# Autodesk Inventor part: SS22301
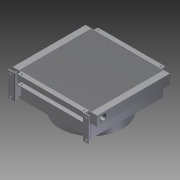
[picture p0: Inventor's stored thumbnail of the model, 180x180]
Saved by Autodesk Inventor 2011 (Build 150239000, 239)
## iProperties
Created: 2011-08
Part Number: SS22301
Document SubType Name: Modeling
Designer: khramov
Density: 1 g/cm^3
Author: khramov
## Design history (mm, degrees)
sketch "Эскиз1"
  geometry: L1 (0, 0)-(54, 0); L2 (538, 0)-(538, -464); L3 (538, -464)-(484, -464); L4 (0, -464)-(0, 0); L5 (0, -232)-(538, -232); L6 (54, 0)-(54, 25); L7 (54, 25)-(484, 25); L8 (484, 25)-(484, 0); L9 (484, 0)-(538, 0); L10 (54, -464)-(54, -489); L11 (54, -489)-(484, -489); L12 (484, -489)-(484, -464); L13 (54, -464)-(0, -464); L14 (70, 12.5)-(468, 12.5); L15 (468, 12.5)-(468, -476.5); L16 (468, -476.5)-(70, -476.5); L17 (70, -476.5)-(70, 12.5); L18 (269, 25)-(269, -489); C1 r 4.5 at (70, 12.5); C2 r 4.5 at (468, 12.5); C3 r 4.5 at (468, -476.5); C4 r 4.5 at (70, -476.5)
  constraints: 36 end point, 7 parallel, 7 perpendicular, 4 centre point, 4 coincident, 4 midpoint, 4 symmetric about line, 3 horizontal, 1 point on line
  dimensions: "d4" = 9 diameter of C4; "d5" = 9 diameter of C3; "d7" = 9 diameter of C1; "d38" = 538 distance between parallel lines of L2 L4; "d39" = 430 distance of L6.end L7.end; "d40" = 54 distance between parallel lines of L6 L4; "d41" = 25 distance of L1.end L6.end; "d42" = 514 distance between parallel lines of L11 L7; "d43" = 489 distance of L16.end L14.start; "d44" = 244.5 distance between parallel lines of L14 L5; "d45" = 398 distance of L14.start L14.end; "d46" = 199 distance between parallel lines of L18 L15; "d47" = 9 diameter of C2
extrude "Выдавливание1" new body sketch "Эскиз1" distance "d13" = 63; taper "d14" = 0 deg
sketch "Эскиз2"
  geometry: L1 (0, 0)-(54, 0) reference; L2 (54, -489)-(54, -464) reference; L3 (484, -464)-(484, -489) reference; L4 (538, -464)-(484, -464) reference; L5 (39, -3)-(499, -3); L6 (499, -3)-(499, -461); L7 (499, -461)-(39, -461); L8 (39, -461)-(39, -3)
  constraints: 8 end point, 2 parallel, 1 horizontal, 1 perpendicular
  dimensions: "d15" = 3 distance between parallel lines of L5 L1; "d16" = 3 distance between parallel lines of L7 L4; "d17" = 15 distance between parallel lines of L6 L3; "d18" = 15 distance between parallel lines of L2 L8
extrude "Выдавливание2" cut sketch "Эскиз2" distance "d19" = 2; taper "d20" = 0 deg
sketch "Эскиз3"
  geometry: L1 (-63, 25)-(-63, 0) reference; L2 (0, 25)-(0, 0) reference; L3 (0, 25)-(-63, 25) reference; L4 (-57, 25)-(-6, 25); L5 (-6, 25)-(-6, 0); L6 (-6, 0)-(-57, 0); L7 (-57, 0)-(-57, 25); L8 (0, -489)-(-63, -489) reference; L9 (-57, -489)-(-6, -489); L10 (-6, -489)-(-6, -464); L11 (-6, -464)-(-57, -464); L12 (-57, -464)-(-57, -489); L13 (0, 0)-(0, -464) reference; L14 (-63, 0)-(-63, -464) reference
  constraints: 16 end point, 4 parallel, 2 horizontal, 2 perpendicular, 2 point on line
  dimensions: "d21" = 6 distance between parallel lines of L7 L1; "d22" = 6 distance between parallel lines of L2 L5; "d23" = 25 distance between parallel lines of L6 L3; "d24" = 25 distance of L9.end L10.end; "d25" = 6 distance between parallel lines of L13 L10; "d26" = 6 distance between parallel lines of L14 L12
extrude "Выдавливание3" cut sketch "Эскиз3" stored distance "d27" = 2; taper "d28" = 0 deg
sketch "Эскиз4"
  geometry: L1 (0, 0)-(-54, 0) reference; L2 (-54, 0)-(-54, 25) reference; L3 (-484, 25)-(-484, 0) reference; L4 (-494, 0)-(-44, 0); L5 (-44, 0)-(-44, -464); L6 (-44, -464)-(-494, -464); L7 (-494, -464)-(-494, 0)
  constraints: 8 end point, 2 parallel, 1 horizontal, 1 perpendicular, 1 point on line
  dimensions: "d48" = 464 distance of L4.end L5.end; "d49" = 10 distance between parallel lines of L3 L7; "d50" = 10 distance between parallel lines of L2 L5
extrude "Выдавливание4" join sketch "Эскиз4" distance "d51" = 90; taper "d52" = 0 deg
sketch "Эскиз5"
  geometry: L1 (-494, 0)-(-44, -464); L2 (-44, 0)-(-494, -464); C1 r 200 at (-269, -232); 1 further point
  constraints: 4 end point, 1 centre point, 1 midpoint
  dimensions: "d53" = 400 diameter of C1
extrude "Выдавливание5" join sketch "Эскиз5" distance "d54" = 70; taper "d55" = 0 deg
sketch "Эскиз6"
  geometry: L1 (-269, -232)-(-269, -734.409); L2 (-484, -489)-(-54, -489) reference; L3 (-538, -464)-(-494, -464) reference; L4 (-491.5, -464)-(-491.5, -494); L5 (-497.5, -500)-(-526.5, -500); L6 (-526.5, -500)-(-526.5, -506); L7 (-526.5, -506)-(-491.5, -506); L8 (-485.5, -500)-(-485.5, -464); L9 (-511.5, -503.753)-(-511.5, -569.856); L10 (-11.5, -500)-(-11.5, -506); L11 (-11.5, -506)-(-46.5, -506); L12 (-40.5, -500)-(-11.5, -500); L13 (-46.5, -464)-(-46.5, -494); L14 (-52.5, -500)-(-52.5, -464); L15 (-26.5, -503.753)-(-26.5, -569.856); L16 (-491.5, -464)-(-485.5, -464); L17 (-538, -464)-(-484, -464) reference; L18 (-52.5, -464)-(-46.5, -464); L19 (-54, -464)-(0, -464) reference; C1 r 200 at (-269, -232) reference; A1 r 6 centre (-497.5, -494) between (-497.5, -500) and (-491.5, -494); A2 r 6 centre (-491.5, -500) between (-491.5, -506) and (-485.5, -500); A3 r 6 centre (-40.5, -494) between (-46.5, -494) and (-40.5, -500); A4 r 6 centre (-46.5, -500) between (-52.5, -500) and (-46.5, -506); 2 further points
  constraints: 31 end point, 13 symmetric about line, 8 point on circle, 4 centre point, 4 tangent, 3 parallel, 2 collinear, 2 perpendicular, 1 equal radius, 1 point on line, 2 other
  dimensions: "d56" = 6 distance of L5.end L6.end; "d57" = 6 distance between parallel lines of L4 L8; "d59" = 15 distance between parallel lines of L9 L6; "d60" = 20 distance between parallel lines of L4 L9; "d62" = 6 radius of A1; "d75" = 485 distance between parallel lines of L9 L15
extrude "Выдавливание6" join sketch "Эскиз6" distance "d63" = 166; taper "d65" = 0 deg; dims "d64" = 1, "d66" = 0
sketch "Эскиз7"
  geometry: L1 (-500, 15)-(-15, 15); L2 (-15, 15)-(-15, 141); L3 (-15, 141)-(-500, 141); L4 (-500, 141)-(-500, 15); L5 (-457.5, 236)-(-57.5, 236) reference; L6 (-257.5, 236)-(-257.5, 402.493); L7 (-472.5, 13)-(-42.5, 13) reference; C1 r 6.5 at (-500, 141); C2 r 6.5 at (-500, 15); C3 r 6.5 at (-15, 141); C4 r 6.5 at (-15, 15); 1 further point
  constraints: 10 end point, 4 centre point, 4 coincident, 2 parallel, 2 perpendicular, 1 horizontal, 1 midpoint
  dimensions: "d67" = 13 diameter of C1; "d68" = 13 diameter of C2; "d69" = 13 diameter of C3; "d70" = 13 diameter of C4; "d71" = 485 distance of L2.end L3.end; "d72" = 126 distance of L3.end L1.start; "d73" = 242.5 distance between parallel lines of L6 L4; "d76" = 2 distance between parallel lines of L1 L7
extrude "Выдавливание7" cut sketch "Эскиз7" distance "d77" = 10; taper "d78" = 0 deg
sketch "Эскиз8"
  geometry: L1 (-166, 15.676)-(-77.058, 26.142); L2 (-77.058, 26.142)-(-77.058, 42); L3 (-166, 42)-(-166, 15.676); L4 (-166, 42)-(-77.058, 42); L5 (-23.748, 26.142)-(-23.748, 42); L6 (-23.748, 42)-(-12.683, 42); L7 (-23.748, 26.142)-(-10, 16.534); L8 (-10, 0)-(0, 0); L9 (0, 0)-(0, 42); L10 (0, 42)-(-23.748, 42); L11 (-10, 16.534)-(-10, 0); 1 further point
  constraints: 22 end point, 3 perpendicular, 1 vertical
  dimensions: "d79" = 10 distance between parallel lines of L9 L11
extrude "Выдавливание8" cut sketch "Эскиз8" stored distance "d80" = 10; taper "d81" = 0 deg
sketch "Эскиз9"
  geometry: L1 (-166, 6)-(-166, 36) reference; L2 (-166, 8.721)-(-166, 36); L3 (-166, 36)-(-77.058, 36); L4 (-77.058, 20.142)-(-77.058, 36) reference; L5 (-77.058, 36)-(-77.058, 20.142); L6 (-77.058, 20.142)-(-166, 9.676); L7 (-77.058, 20.142)-(-166, 9.676) reference; L8 (0, 36)-(0, -6); L9 (0, 36)-(0, 0) reference; L10 (0, -6)-(-10, -6); L11 (-10, -6)-(-10, 0) reference; L12 (-10, -6)-(-10, 10.534); L13 (-10, 10.534)-(-23.748, 20.142); L14 (-10, 10.534)-(-23.748, 20.142) reference; L15 (-23.748, 20.142)-(-23.748, 36); L16 (-153, 36)-(0, 36) reference; L17 (-23.748, 36)-(0, 36); 1 further point
  constraints: 20 end point, 6 collinear, 2 parallel, 2 perpendicular, 2 point on line
extrude "Выдавливание9" cut sketch "Эскиз9" stored distance "d82" = 10; taper "d83" = 0 deg
sketch "Эскиз10"
  geometry: L1 (0, 464)-(63, 464) reference; L2 (0, 0)-(63, 0) reference; L3 (31.5, 464)-(31.5, 0); L4 (-80, -42)-(76, -42) reference; 1 further point
  constraints: 2 end point, 2 midpoint, 1 point on line
  dimensions: "d104" = 468.5 distance from line of L4 point (31.5, 426.5)
hole "Отверстие1" sketch "Эскиз10" at (31.5, 426.5) diameter "d86" = 38.952; stored, may be unused: countersink angle "d90" = 90 deg, drill point angle "d92" = 118 deg; dims "d87" = 45, "d88" = 42, "d89" = 2, "d91" = 50
sketch "Эскиз14"
  geometry: L1 (80, -42)-(-76, -42) reference; L2 (-31.5, 379.038)-(-31.5, 0); 1 further point
  constraints: 2 end point, 1 point on line
  dimensions: "d105" = 81.5 distance from line of L1 point (-31.5, 39.5)
hole "Отверстие2" sketch "Эскиз14" at (-31.5, 39.5) diameter "d106" = 38.952; stored, may be unused: countersink angle "d110" = 90 deg, drill point angle "d112" = 118 deg; dims "d107" = 45, "d108" = 42, "d109" = 2, "d111" = 50
node "Твердое тело1"
